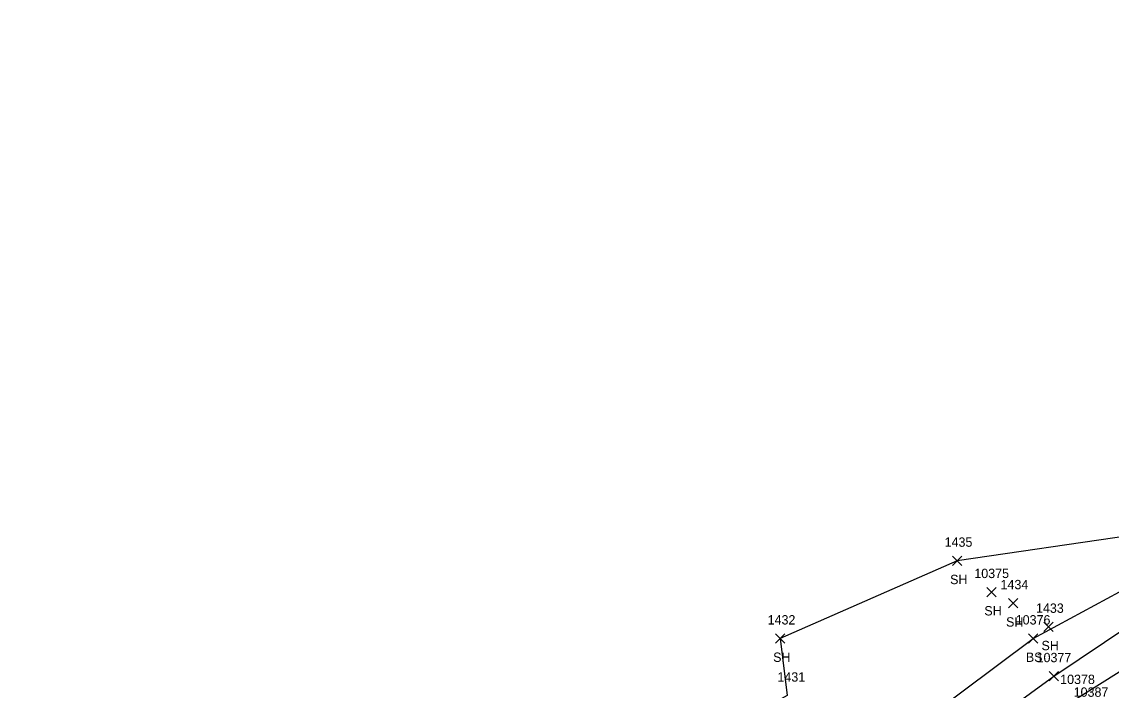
# Model space of a CAD drawing. Extents: x 1651685 to 1653558, y 889533 to 891085.
# Drawn here: x 1652738.2 to 1652971.5, y 890725 to 890868.1 of the extents above; entities that cross this region are included whole.
import ezdxf

# ---------------------------------------------------------------- set-up
doc = ezdxf.new("R2010")
doc.units = 0
for name, color, linetype in [('L_A', 7, 'Continuous'), ('L_I', 7, 'Continuous'), ('L_TIC', 7, 'Continuous'), ('LAWA', 7, 'Continuous'), ('LELB', 7, 'Continuous'), ('LSOGP', 7, 'Continuous'), ('R_I', 7, 'Continuous')]:
    doc.layers.add(name, color=color, linetype=linetype)

msp = doc.modelspace()

# ---------------------------------------------------------------- linework, layer by layer
at = {"layer": 'L_TIC'}
for points in [[(1652937.51, 890751.73), (1652939.51, 890753.73)], [(1652939.51, 890751.73), (1652937.51, 890753.73)], [(1652944.85, 890745.03), (1652946.85, 890747.03)], [(1652946.85, 890745.03), (1652944.85, 890747.03)], [(1652949.49, 890742.64), (1652951.49, 890744.64)], [(1652951.49, 890742.64), (1652949.49, 890744.64)], [(1652957.08, 890737.59), (1652959.08, 890739.59)], [(1652959.08, 890737.59), (1652957.08, 890739.59)], [(1652899.61, 890735.09), (1652901.61, 890737.09)], [(1652901.61, 890735.09), (1652899.61, 890737.09)], [(1652953.78, 890735.09), (1652955.78, 890737.09)], [(1652955.78, 890735.09), (1652953.78, 890737.09)], [(1652958.19, 890727.02), (1652960.19, 890729.02)], [(1652960.19, 890727.02), (1652958.19, 890729.02)]]:
    msp.add_lwpolyline(points, dxfattribs=at)
at = {"layer": 'LAWA'}
msp.add_lwpolyline([(1652817.98, 890613.54), (1652840.14, 890627.46), (1652861.15, 890647.29), (1652878.51, 890666.18), (1652884.26, 890671.52), (1652922.69, 890701.4), (1652959.19, 890728.02), (1652986.15, 890746.08), (1653025.9, 890769.89), (1653049.43, 890788.17), (1653075.47, 890803.38), (1653097.52, 890818.66), (1653132.33, 890844.48)], dxfattribs=at)
at = {"layer": 'LELB'}
for points in [[(1652773.03, 890464.56), (1652787.9, 890509.35), (1652802.92, 890548.75), (1652814.17, 890571.87), (1652832.16, 890602.17), (1652848.73, 890624.66), (1652866.01, 890644.23), (1652889.12, 890668.57), (1652926.33, 890696.32), (1652964.24, 890723.35), (1652991.22, 890740.2), (1653028.13, 890766.86), (1653057.75, 890784.91), (1653079.01, 890799.53), (1653102.53, 890813.78), (1653139.28, 890840.79)], [(1652740.63, 890407.57), (1652746.83, 890413.23), (1652755.32, 890445.88), (1652760.35, 890468.2), (1652780.77, 890512.23), (1652796.45, 890551.5), (1652807.59, 890577.74), (1652825.47, 890605.79), (1652840.14, 890627.46), (1652854.42, 890651.04), (1652870.71, 890668.15), (1652876.32, 890668.87), (1652880.71, 890674.05), (1652916.29, 890707.34), (1652954.78, 890736.09), (1652983.82, 890751.78), (1653022.66, 890774.83), (1653049.43, 890788.17)]]:
    msp.add_lwpolyline(points, dxfattribs=at)
at = {"layer": 'LSOGP'}
msp.add_lwpolyline([(1653191.35, 890868.11), (1653139.25, 890847.21), (1653133.81, 890854.84), (1653132.26, 890853.62), (1653128.23, 890850.65), (1653088.88, 890824.36), (1653067.93, 890808.39), (1653036.42, 890796.38), (1653023.39, 890789.29), (1652975.72, 890758.11), (1652938.51, 890752.73), (1652900.6, 890736.09), (1652902.13, 890723.86), (1652868.79, 890705.34), (1652839.11, 890687.76), (1652822.21, 890657.08), (1652787.43, 890617.81), (1652783.5, 890592.65), (1652777.63, 890568.95), (1652768.73, 890549.07), (1652760.18, 890544.48), (1652755.23, 890514.52), (1652738.16, 890487.37)], dxfattribs=at)

# ---------------------------------------------------------------- texts
at = {"layer": 'L_A'}
for s, p in [('SH', (1652937, 890747.73)), ('SH', (1652944.33, 890741.03)), ('SH', (1652948.98, 890738.64)), ('SH', (1652956.57, 890733.59)), ('SH', (1652899.09, 890731.09)), ('BS', (1652953.22, 890731.09))]:
    msp.add_text(s, height=2, dxfattribs=at).set_placement(p)
at = {"layer": 'L_I'}
for s, p in [('1435', (1652935.82, 890755.73)), ('10375', (1652942.18, 890749.03)), ('1434', (1652947.8, 890746.64)), ('1433', (1652955.39, 890741.59)), ('1432', (1652897.91, 890739.09)), ('10376', (1652951.05, 890739.09)), ('10377', (1652955.52, 890731.02)), ('1431', (1652900.01, 890726.86)), ('10378', (1652960.57, 890726.35))]:
    msp.add_text(s, height=2, dxfattribs=at).set_placement(p)
at = {"layer": 'R_I'}
msp.add_text('10387', height=2, dxfattribs=at).set_placement((1652963.46, 890723.62))

doc.saveas('drawing.dxf')
